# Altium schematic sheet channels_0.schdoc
size 400 x 299 mm; Device: default420x319; Symbol: default420x319; Name: default420x319; Size: "User"; Id: /; File: channels_0; Sheet: /
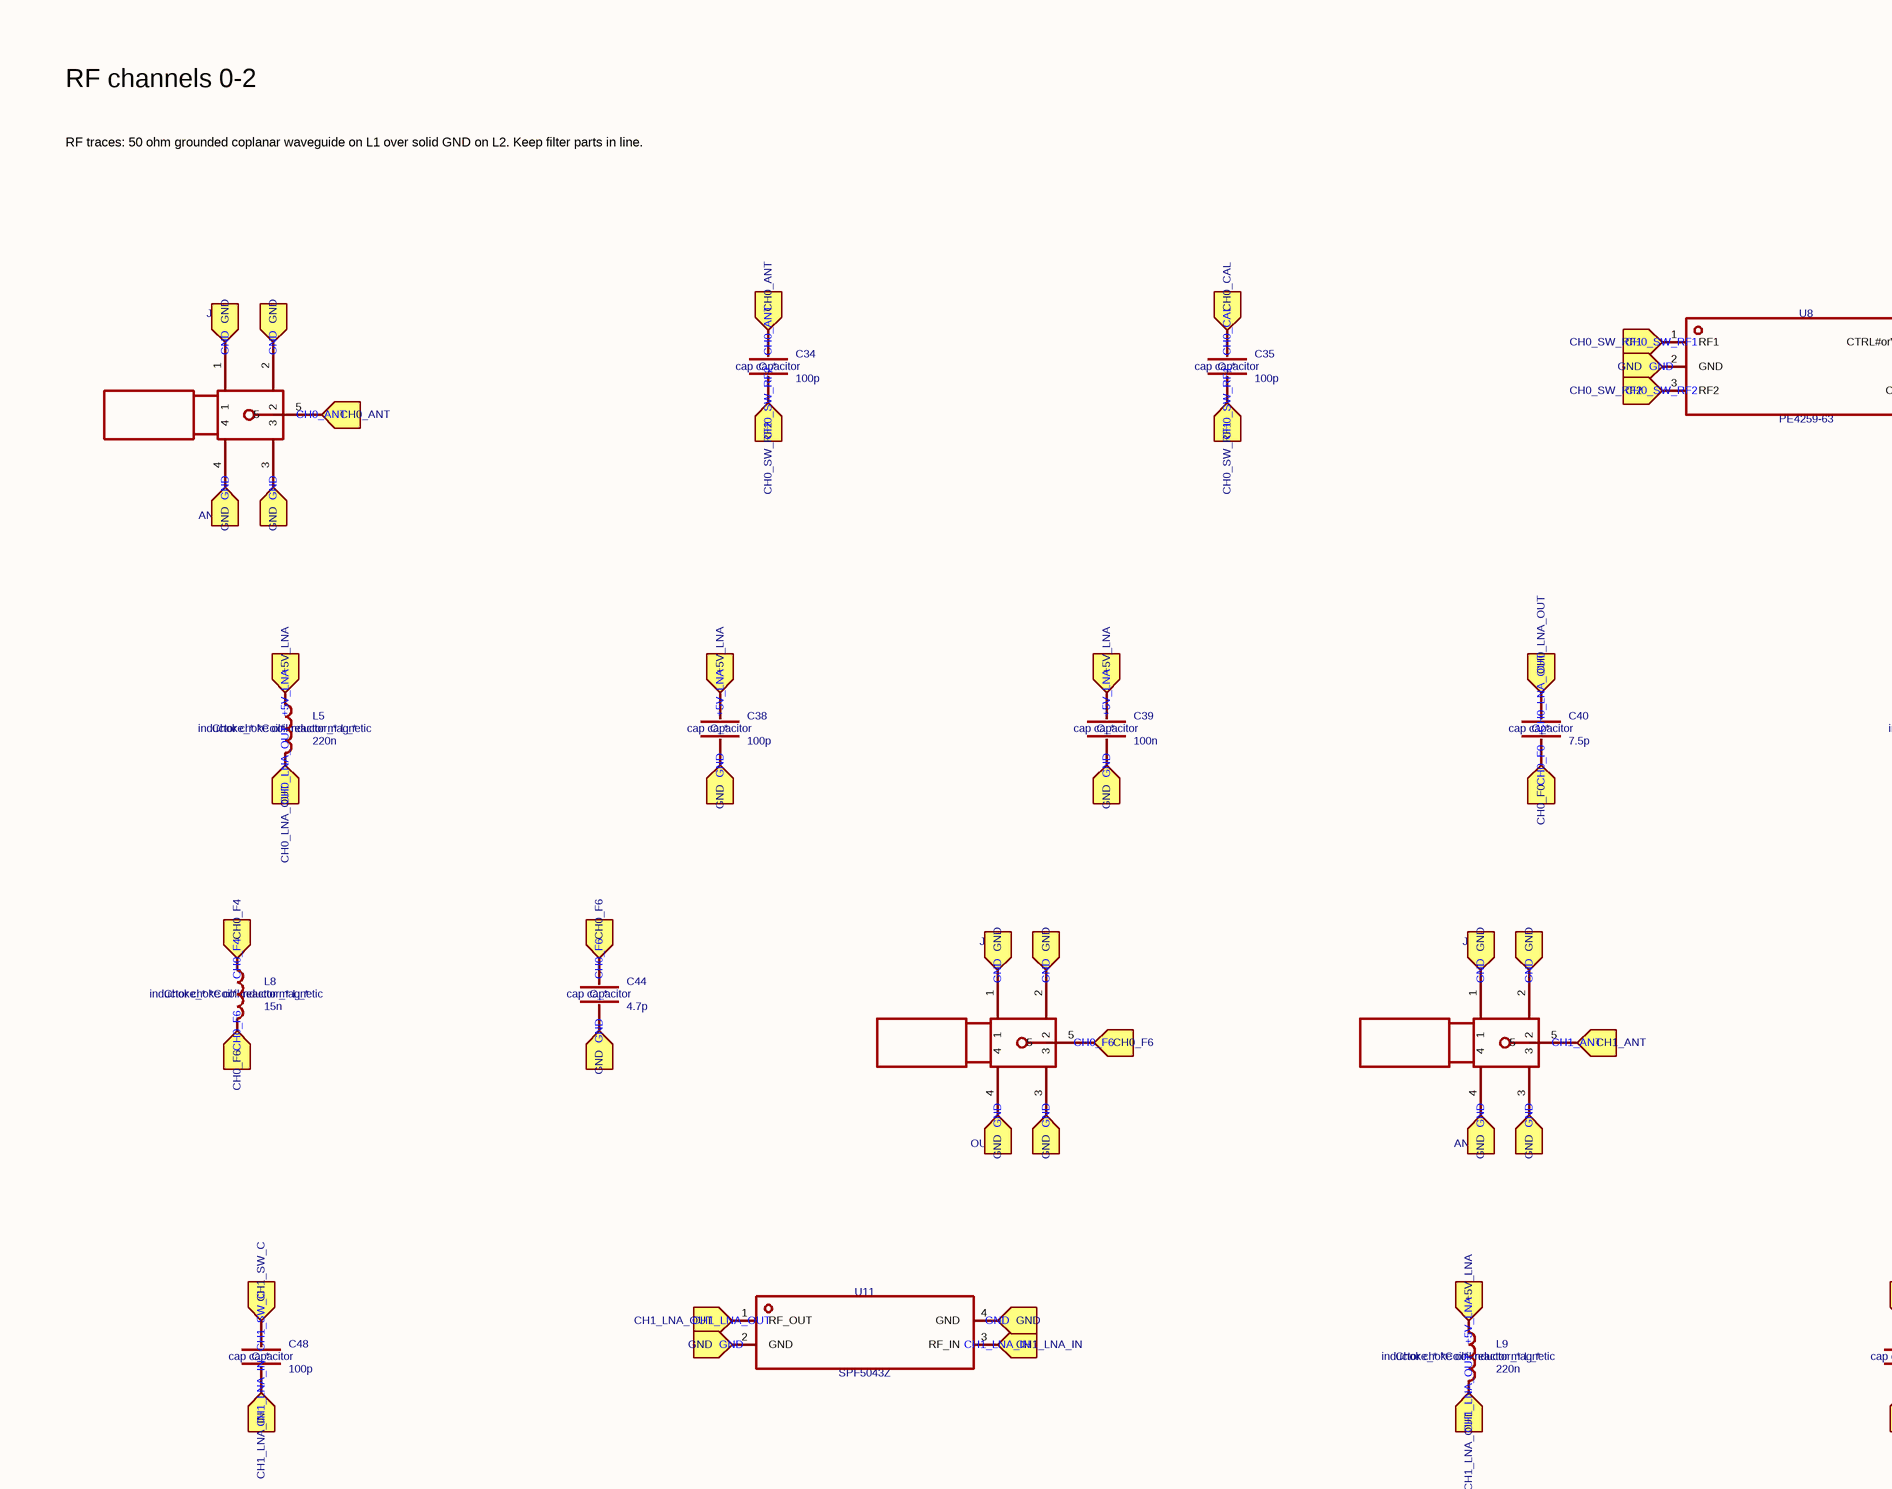
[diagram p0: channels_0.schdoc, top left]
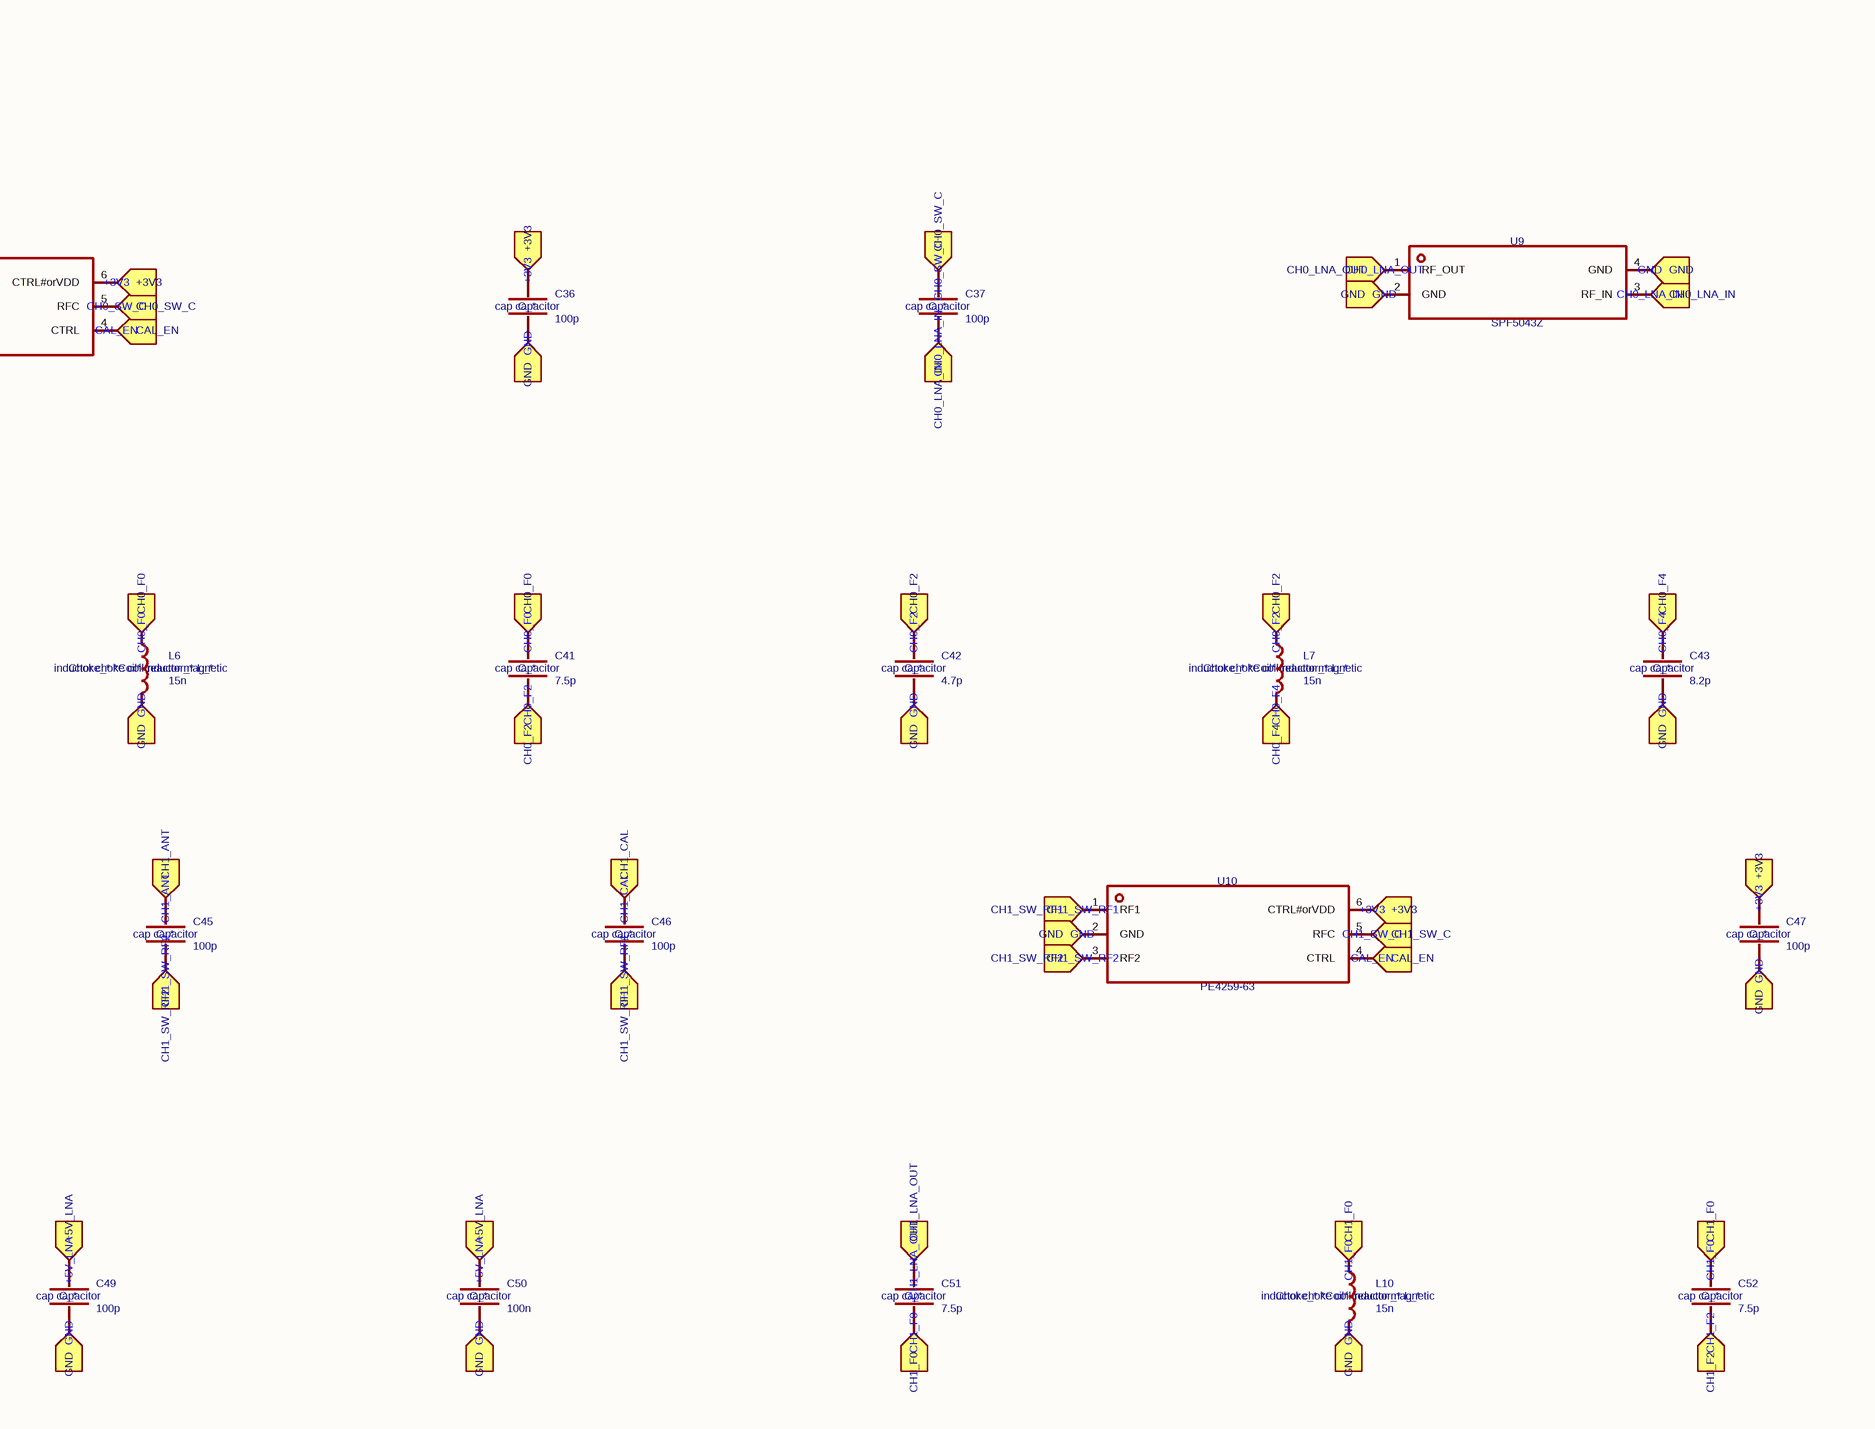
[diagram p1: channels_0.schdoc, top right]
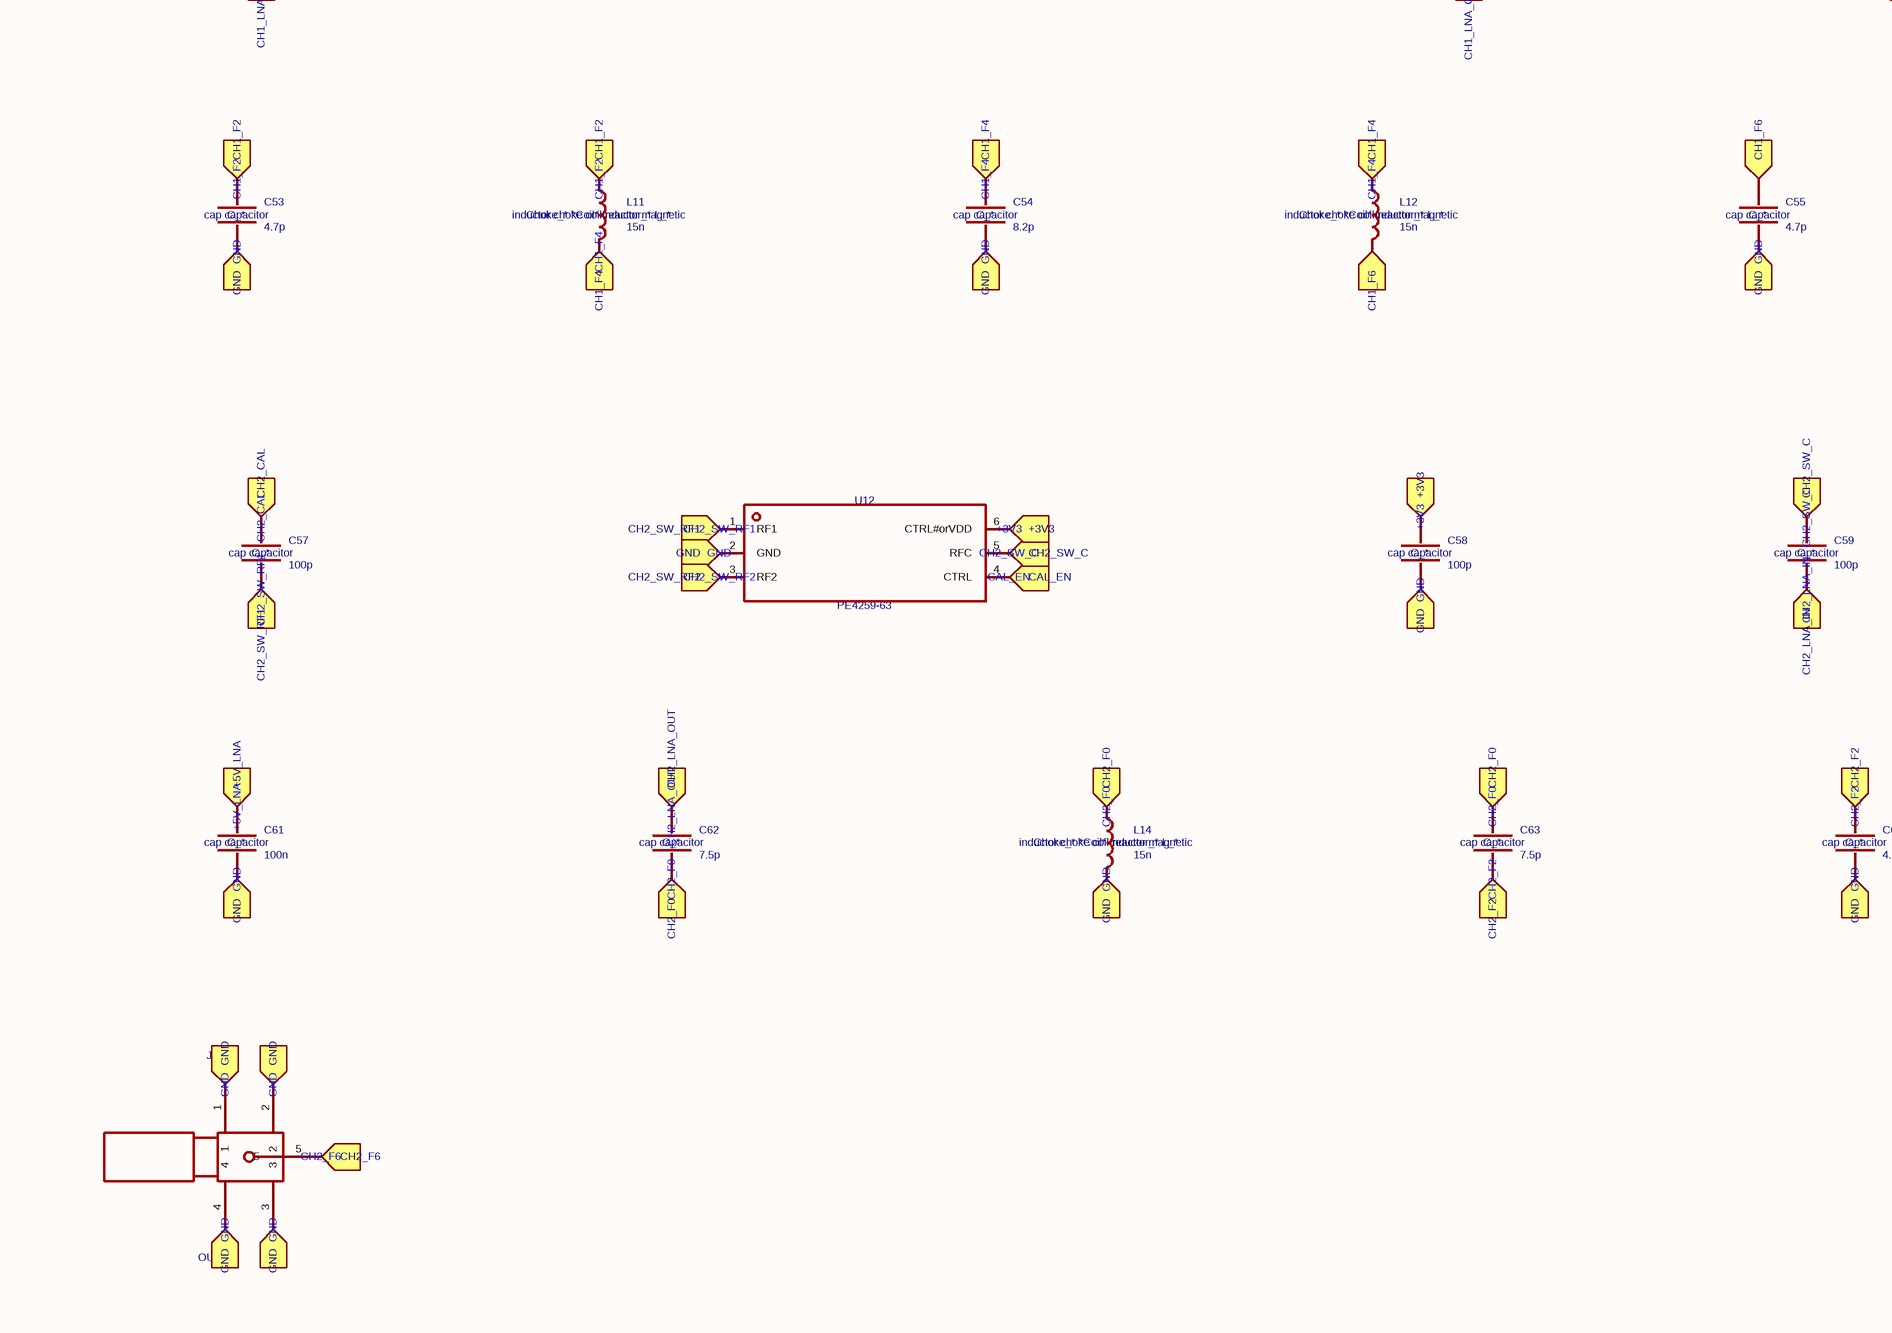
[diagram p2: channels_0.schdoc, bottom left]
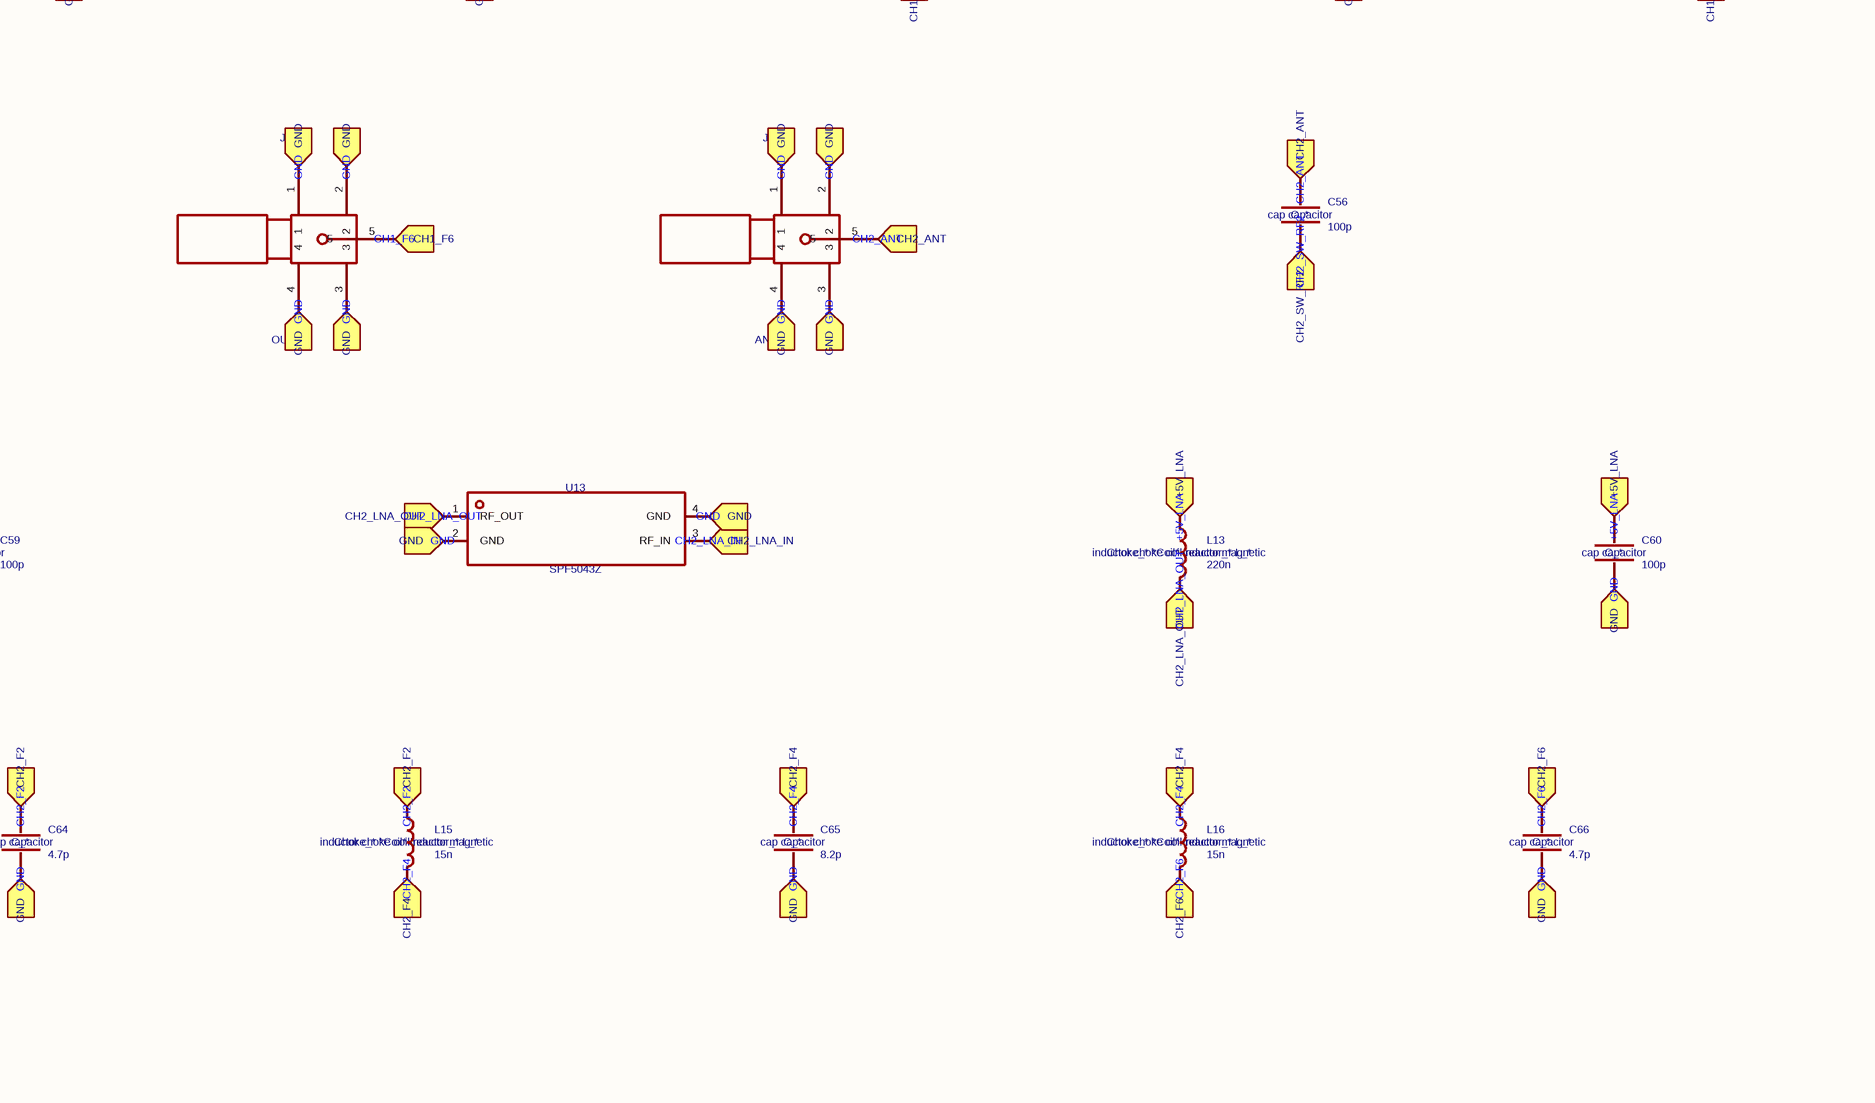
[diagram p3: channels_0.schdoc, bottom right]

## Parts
C34  value 100p  ki_keywords: cap capacitor  ki_fp_filters: C_*  [Capacitor_SMD:C_0402_1005Metric]  (hidden comment: Device_C)
C35  value 100p  ki_keywords: cap capacitor  ki_fp_filters: C_*  [Capacitor_SMD:C_0402_1005Metric]  (hidden comment: Device_C)
C36  value 100p  ki_keywords: cap capacitor  ki_fp_filters: C_*  [Capacitor_SMD:C_0402_1005Metric]  (hidden comment: Device_C)
C37  value 100p  ki_keywords: cap capacitor  ki_fp_filters: C_*  [Capacitor_SMD:C_0402_1005Metric]  (hidden comment: Device_C)
C38  value 100p  ki_keywords: cap capacitor  ki_fp_filters: C_*  [Capacitor_SMD:C_0402_1005Metric]  (hidden comment: Device_C)
C39  value 100n  ki_keywords: cap capacitor  ki_fp_filters: C_*  [Capacitor_SMD:C_0402_1005Metric]  (hidden comment: Device_C)
C40  value 7.5p  ki_keywords: cap capacitor  ki_fp_filters: C_*  [Capacitor_SMD:C_0402_1005Metric]  (hidden comment: Device_C)
C41  value 7.5p  ki_keywords: cap capacitor  ki_fp_filters: C_*  [Capacitor_SMD:C_0402_1005Metric]  (hidden comment: Device_C)
C42  value 4.7p  ki_keywords: cap capacitor  ki_fp_filters: C_*  [Capacitor_SMD:C_0402_1005Metric]  (hidden comment: Device_C)
C43  value 8.2p  ki_keywords: cap capacitor  ki_fp_filters: C_*  [Capacitor_SMD:C_0402_1005Metric]  (hidden comment: Device_C)
C44  value 4.7p  ki_keywords: cap capacitor  ki_fp_filters: C_*  [Capacitor_SMD:C_0402_1005Metric]  (hidden comment: Device_C)
C45  value 100p  ki_keywords: cap capacitor  ki_fp_filters: C_*  [Capacitor_SMD:C_0402_1005Metric]  (hidden comment: Device_C)
C46  value 100p  ki_keywords: cap capacitor  ki_fp_filters: C_*  [Capacitor_SMD:C_0402_1005Metric]  (hidden comment: Device_C)
C47  value 100p  ki_keywords: cap capacitor  ki_fp_filters: C_*  [Capacitor_SMD:C_0402_1005Metric]  (hidden comment: Device_C)
C48  value 100p  ki_keywords: cap capacitor  ki_fp_filters: C_*  [Capacitor_SMD:C_0402_1005Metric]  (hidden comment: Device_C)
C49  value 100p  ki_keywords: cap capacitor  ki_fp_filters: C_*  [Capacitor_SMD:C_0402_1005Metric]  (hidden comment: Device_C)
C50  value 100n  ki_keywords: cap capacitor  ki_fp_filters: C_*  [Capacitor_SMD:C_0402_1005Metric]  (hidden comment: Device_C)
C51  value 7.5p  ki_keywords: cap capacitor  ki_fp_filters: C_*  [Capacitor_SMD:C_0402_1005Metric]  (hidden comment: Device_C)
C52  value 7.5p  ki_keywords: cap capacitor  ki_fp_filters: C_*  [Capacitor_SMD:C_0402_1005Metric]  (hidden comment: Device_C)
C53  value 4.7p  ki_keywords: cap capacitor  ki_fp_filters: C_*  [Capacitor_SMD:C_0402_1005Metric]  (hidden comment: Device_C)
C54  value 8.2p  ki_keywords: cap capacitor  ki_fp_filters: C_*  [Capacitor_SMD:C_0402_1005Metric]  (hidden comment: Device_C)
C55  value 4.7p  ki_keywords: cap capacitor  ki_fp_filters: C_*  [Capacitor_SMD:C_0402_1005Metric]  (hidden comment: Device_C)
C56  value 100p  ki_keywords: cap capacitor  ki_fp_filters: C_*  [Capacitor_SMD:C_0402_1005Metric]  (hidden comment: Device_C)
C57  value 100p  ki_keywords: cap capacitor  ki_fp_filters: C_*  [Capacitor_SMD:C_0402_1005Metric]  (hidden comment: Device_C)
C58  value 100p  ki_keywords: cap capacitor  ki_fp_filters: C_*  [Capacitor_SMD:C_0402_1005Metric]  (hidden comment: Device_C)
C59  value 100p  ki_keywords: cap capacitor  ki_fp_filters: C_*  [Capacitor_SMD:C_0402_1005Metric]  (hidden comment: Device_C)
C60  value 100p  ki_keywords: cap capacitor  ki_fp_filters: C_*  [Capacitor_SMD:C_0402_1005Metric]  (hidden comment: Device_C)
C61  value 100n  ki_keywords: cap capacitor  ki_fp_filters: C_*  [Capacitor_SMD:C_0402_1005Metric]  (hidden comment: Device_C)
C62  value 7.5p  ki_keywords: cap capacitor  ki_fp_filters: C_*  [Capacitor_SMD:C_0402_1005Metric]  (hidden comment: Device_C)
C63  value 7.5p  ki_keywords: cap capacitor  ki_fp_filters: C_*  [Capacitor_SMD:C_0402_1005Metric]  (hidden comment: Device_C)
C64  value 4.7p  ki_keywords: cap capacitor  ki_fp_filters: C_*  [Capacitor_SMD:C_0402_1005Metric]  (hidden comment: Device_C)
C65  value 8.2p  ki_keywords: cap capacitor  ki_fp_filters: C_*  [Capacitor_SMD:C_0402_1005Metric]  (hidden comment: Device_C)
C66  value 4.7p  ki_keywords: cap capacitor  ki_fp_filters: C_*  [Capacitor_SMD:C_0402_1005Metric]  (hidden comment: Device_C)
J3  value ANT0  [prc:SMA-TH_BWSMA-KE-Z001]  (hidden comment: prc_BWSMA-KE-Z001)
J4  value OUT0  [prc:SMA-TH_BWSMA-KE-Z001]  (hidden comment: prc_BWSMA-KE-Z001)
J5  value ANT1  [prc:SMA-TH_BWSMA-KE-Z001]  (hidden comment: prc_BWSMA-KE-Z001)
J6  value OUT1  [prc:SMA-TH_BWSMA-KE-Z001]  (hidden comment: prc_BWSMA-KE-Z001)
J7  value ANT2  [prc:SMA-TH_BWSMA-KE-Z001]  (hidden comment: prc_BWSMA-KE-Z001)
J8  value OUT2  [prc:SMA-TH_BWSMA-KE-Z001]  (hidden comment: prc_BWSMA-KE-Z001)
L5  value 220n  ki_keywords: inductor choke coil reactor magnetic  ki_fp_filters: Choke_* *Coil* Inductor_* L_*  [Inductor_SMD:L_0603_1608Metric]  (hidden comment: Device_L)
L6  value 15n  ki_keywords: inductor choke coil reactor magnetic  ki_fp_filters: Choke_* *Coil* Inductor_* L_*  [Inductor_SMD:L_0402_1005Metric]  (hidden comment: Device_L)
L7  value 15n  ki_keywords: inductor choke coil reactor magnetic  ki_fp_filters: Choke_* *Coil* Inductor_* L_*  [Inductor_SMD:L_0402_1005Metric]  (hidden comment: Device_L)
L8  value 15n  ki_keywords: inductor choke coil reactor magnetic  ki_fp_filters: Choke_* *Coil* Inductor_* L_*  [Inductor_SMD:L_0402_1005Metric]  (hidden comment: Device_L)
L9  value 220n  ki_keywords: inductor choke coil reactor magnetic  ki_fp_filters: Choke_* *Coil* Inductor_* L_*  [Inductor_SMD:L_0603_1608Metric]  (hidden comment: Device_L)
L10  value 15n  ki_keywords: inductor choke coil reactor magnetic  ki_fp_filters: Choke_* *Coil* Inductor_* L_*  [Inductor_SMD:L_0402_1005Metric]  (hidden comment: Device_L)
L11  value 15n  ki_keywords: inductor choke coil reactor magnetic  ki_fp_filters: Choke_* *Coil* Inductor_* L_*  [Inductor_SMD:L_0402_1005Metric]  (hidden comment: Device_L)
L12  value 15n  ki_keywords: inductor choke coil reactor magnetic  ki_fp_filters: Choke_* *Coil* Inductor_* L_*  [Inductor_SMD:L_0402_1005Metric]  (hidden comment: Device_L)
L13  value 220n  ki_keywords: inductor choke coil reactor magnetic  ki_fp_filters: Choke_* *Coil* Inductor_* L_*  [Inductor_SMD:L_0603_1608Metric]  (hidden comment: Device_L)
L14  value 15n  ki_keywords: inductor choke coil reactor magnetic  ki_fp_filters: Choke_* *Coil* Inductor_* L_*  [Inductor_SMD:L_0402_1005Metric]  (hidden comment: Device_L)
L15  value 15n  ki_keywords: inductor choke coil reactor magnetic  ki_fp_filters: Choke_* *Coil* Inductor_* L_*  [Inductor_SMD:L_0402_1005Metric]  (hidden comment: Device_L)
L16  value 15n  ki_keywords: inductor choke coil reactor magnetic  ki_fp_filters: Choke_* *Coil* Inductor_* L_*  [Inductor_SMD:L_0402_1005Metric]  (hidden comment: Device_L)
U8  value PE4259-63  [prc:SC-70-6_L2.2-W1.3-P0.65-LS2.1-BL]  (hidden comment: prc_PE4259-63)
U9  value SPF5043Z  [prc:SOT343_L2.0-W1.3-P1.30-LS2.1-BL]  (hidden comment: prc_SPF5043Z)
U10  value PE4259-63  [prc:SC-70-6_L2.2-W1.3-P0.65-LS2.1-BL]  (hidden comment: prc_PE4259-63)
U11  value SPF5043Z  [prc:SOT343_L2.0-W1.3-P1.30-LS2.1-BL]  (hidden comment: prc_SPF5043Z)
U12  value PE4259-63  [prc:SC-70-6_L2.2-W1.3-P0.65-LS2.1-BL]  (hidden comment: prc_PE4259-63)
U13  value SPF5043Z  [prc:SOT343_L2.0-W1.3-P1.30-LS2.1-BL]  (hidden comment: prc_SPF5043Z)

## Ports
+3V3 (in), +5V_LNA (in), CAL_EN (in), CH0_ANT (in), CH0_CAL (in), CH0_F0 (in), CH0_F2 (in), CH0_F4 (in), CH0_F6 (in), CH0_LNA_IN (in), CH0_LNA_OUT (in), CH0_SW_C (in), CH0_SW_RF1 (in), CH0_SW_RF2 (in), CH1_ANT (in), CH1_CAL (in), CH1_F0 (in), CH1_F2 (in), CH1_F4 (in), CH1_F6 (in), CH1_LNA_IN (in), CH1_LNA_OUT (in), CH1_SW_C (in), CH1_SW_RF1 (in), CH1_SW_RF2 (in), CH2_ANT (in), CH2_CAL (in), CH2_F0 (in), CH2_F2 (in), CH2_F4 (in), CH2_F6 (in), CH2_LNA_IN (in), CH2_LNA_OUT (in), CH2_SW_C (in), CH2_SW_RF1 (in), CH2_SW_RF2 (in), GND (in)

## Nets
+3V3: C36.1 C47.1 C58.1 U8.6(CTRL#orVDD) U10.6(CTRL#orVDD) U12.6(CTRL#orVDD) ; port +3V3
+5V_LNA: C38.1 C39.1 C49.1 C50.1 C60.1 C61.1 L5.1 L9.1 L13.1 ; port +5V_LNA
CAL_EN: U8.4(CTRL) U10.4(CTRL) U12.4(CTRL) ; port CAL_EN
CH0_ANT: C34.1 J3.5 ; port CH0_ANT
CH0_CAL: C35.1 ; port CH0_CAL
CH0_F0: C40.2 C41.1 L6.1 ; port CH0_F0
CH0_F2: C41.2 C42.1 L7.1 ; port CH0_F2
CH0_F4: C43.1 L7.2 L8.1 ; port CH0_F4
CH0_F6: C44.1 J4.5 L8.2 ; port CH0_F6
CH0_LNA_IN: C37.2 U9.3(RF_IN) ; port CH0_LNA_IN
CH0_LNA_OUT: C40.1 L5.2 U9.1(RF_OUT) ; port CH0_LNA_OUT
CH0_SW_C: C37.1 U8.5(RFC) ; port CH0_SW_C
CH0_SW_RF1: C35.2 U8.1(RF1) ; port CH0_SW_RF1
CH0_SW_RF2: C34.2 U8.3(RF2) ; port CH0_SW_RF2
CH1_ANT: C45.1 J5.5 ; port CH1_ANT
CH1_CAL: C46.1 ; port CH1_CAL
CH1_F0: C51.2 C52.1 L10.1 ; port CH1_F0
CH1_F2: C52.2 C53.1 L11.1 ; port CH1_F2
CH1_F4: C54.1 L11.2 L12.1 ; port CH1_F4
CH1_F6: C55.1 J6.5 L12.2 ; port CH1_F6
CH1_LNA_IN: C48.2 U11.3(RF_IN) ; port CH1_LNA_IN
CH1_LNA_OUT: C51.1 L9.2 U11.1(RF_OUT) ; port CH1_LNA_OUT
CH1_SW_C: C48.1 U10.5(RFC) ; port CH1_SW_C
CH1_SW_RF1: C46.2 U10.1(RF1) ; port CH1_SW_RF1
CH1_SW_RF2: C45.2 U10.3(RF2) ; port CH1_SW_RF2
CH2_ANT: C56.1 J7.5 ; port CH2_ANT
CH2_CAL: C57.1 ; port CH2_CAL
CH2_F0: C62.2 C63.1 L14.1 ; port CH2_F0
CH2_F2: C63.2 C64.1 L15.1 ; port CH2_F2
CH2_F4: C65.1 L15.2 L16.1 ; port CH2_F4
CH2_F6: C66.1 J8.5 L16.2 ; port CH2_F6
CH2_LNA_IN: C59.2 U13.3(RF_IN) ; port CH2_LNA_IN
CH2_LNA_OUT: C62.1 L13.2 U13.1(RF_OUT) ; port CH2_LNA_OUT
CH2_SW_C: C59.1 U12.5(RFC) ; port CH2_SW_C
CH2_SW_RF1: C57.2 U12.1(RF1) ; port CH2_SW_RF1
CH2_SW_RF2: C56.2 U12.3(RF2) ; port CH2_SW_RF2
GND: C36.2 C38.2 C39.2 C42.2 C43.2 C44.2 C47.2 C49.2 C50.2 C53.2 C54.2 C55.2 C58.2 C60.2 C61.2 C64.2 C65.2 C66.2 J3.1 J3.2 J3.3 J3.4 J4.1 J4.2 J4.3 J4.4 J5.1 J5.2 J5.3 J5.4 J6.1 J6.2 J6.3 J6.4 J7.1 J7.2 J7.3 J7.4 J8.1 J8.2 J8.3 J8.4 L6.2 L10.2 L14.2 U8.2(GND) U9.2(GND) U9.4(GND) U10.2(GND) U11.2(GND) U11.4(GND) U12.2(GND) U13.2(GND) U13.4(GND) ; port GND

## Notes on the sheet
- RF channels 0-2
- RF traces: 50 ohm grounded coplanar waveguide on L1 over solid GND on L2. Keep filter parts in line.

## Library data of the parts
C34 = Device_C: UniqueId: 553def7d7947fca6; KiLib_Generator: SMD_2terminal_chip_molded; AddInBom: yes
C35 = Device_C: UniqueId: 2b4e6e580c7acde0; KiLib_Generator: SMD_2terminal_chip_molded; AddInBom: yes
C36 = Device_C: UniqueId: 3db1f6a400993974; KiLib_Generator: SMD_2terminal_chip_molded; AddInBom: yes
C37 = Device_C: UniqueId: ff078052695da6b6; KiLib_Generator: SMD_2terminal_chip_molded; AddInBom: yes
C38 = Device_C: UniqueId: 6827ca7a6bd67e26; KiLib_Generator: SMD_2terminal_chip_molded; AddInBom: yes
C39 = Device_C: UniqueId: 54d3d224326b3f8f; KiLib_Generator: SMD_2terminal_chip_molded; AddInBom: yes
C40 = Device_C: UniqueId: 12af2948e5a85261; KiLib_Generator: SMD_2terminal_chip_molded; AddInBom: yes
C41 = Device_C: UniqueId: c9655d0faea7d93e; KiLib_Generator: SMD_2terminal_chip_molded; AddInBom: yes
C42 = Device_C: UniqueId: d39ee3bf0fadc3c1; KiLib_Generator: SMD_2terminal_chip_molded; AddInBom: yes
C43 = Device_C: UniqueId: ad7e9e1612356ddb; KiLib_Generator: SMD_2terminal_chip_molded; AddInBom: yes
C44 = Device_C: UniqueId: 49133e3f49d3504d; KiLib_Generator: SMD_2terminal_chip_molded; AddInBom: yes
C45 = Device_C: UniqueId: 9dabde1b2911a551; KiLib_Generator: SMD_2terminal_chip_molded; AddInBom: yes
C46 = Device_C: UniqueId: df918f74c5ced612; KiLib_Generator: SMD_2terminal_chip_molded; AddInBom: yes
C47 = Device_C: UniqueId: 64621f1995cfd5bc; KiLib_Generator: SMD_2terminal_chip_molded; AddInBom: yes
C48 = Device_C: UniqueId: 808ebf677d8d6d64; KiLib_Generator: SMD_2terminal_chip_molded; AddInBom: yes
C49 = Device_C: UniqueId: 91fd74edebd22ea1; KiLib_Generator: SMD_2terminal_chip_molded; AddInBom: yes
C50 = Device_C: UniqueId: 32f6df7045cd6eaa; KiLib_Generator: SMD_2terminal_chip_molded; AddInBom: yes
C51 = Device_C: UniqueId: d35436b77a732af0; KiLib_Generator: SMD_2terminal_chip_molded; AddInBom: yes
C52 = Device_C: UniqueId: 35d858017be1d91e; KiLib_Generator: SMD_2terminal_chip_molded; AddInBom: yes
C53 = Device_C: UniqueId: af7046427a4bfdfb; KiLib_Generator: SMD_2terminal_chip_molded; AddInBom: yes
C54 = Device_C: UniqueId: 65328433fb04ddb7; KiLib_Generator: SMD_2terminal_chip_molded; AddInBom: yes
C55 = Device_C: UniqueId: 82ba1af55b3917e5; KiLib_Generator: SMD_2terminal_chip_molded; AddInBom: yes
C56 = Device_C: UniqueId: a22d741cda083e99; KiLib_Generator: SMD_2terminal_chip_molded; AddInBom: yes
C57 = Device_C: UniqueId: 21dd5459dde3f81c; KiLib_Generator: SMD_2terminal_chip_molded; AddInBom: yes
C58 = Device_C: UniqueId: 6c1fb86984bf7302; KiLib_Generator: SMD_2terminal_chip_molded; AddInBom: yes
C59 = Device_C: UniqueId: 9b91e7356bb9865f; KiLib_Generator: SMD_2terminal_chip_molded; AddInBom: yes
C60 = Device_C: UniqueId: 769677d4f8f56233; KiLib_Generator: SMD_2terminal_chip_molded; AddInBom: yes
C61 = Device_C: UniqueId: 3745dda5a27601a3; KiLib_Generator: SMD_2terminal_chip_molded; AddInBom: yes
C62 = Device_C: UniqueId: 4b556904310d1556; KiLib_Generator: SMD_2terminal_chip_molded; AddInBom: yes
C63 = Device_C: UniqueId: b3cb865a57c4a975; KiLib_Generator: SMD_2terminal_chip_molded; AddInBom: yes
C64 = Device_C: UniqueId: 9944326385f1aa7b; KiLib_Generator: SMD_2terminal_chip_molded; AddInBom: yes
C65 = Device_C: UniqueId: ac9f836745bfd3f0; KiLib_Generator: SMD_2terminal_chip_molded; AddInBom: yes
C66 = Device_C: UniqueId: fb27f7370dbf7a2e; KiLib_Generator: SMD_2terminal_chip_molded; AddInBom: yes
J3 = prc_BWSMA-KE-Z001: Manufacturer: BAT WIRELESS(蝙蝠无线); ki_keywords: RF Connectors / Coaxial Connectors; UniqueId: bd3ee0abdb58119f; AddInBom: yes
J4 = prc_BWSMA-KE-Z001: Manufacturer: BAT WIRELESS(蝙蝠无线); ki_keywords: RF Connectors / Coaxial Connectors; UniqueId: 7aadee231938cadd; AddInBom: yes
J5 = prc_BWSMA-KE-Z001: Manufacturer: BAT WIRELESS(蝙蝠无线); ki_keywords: RF Connectors / Coaxial Connectors; UniqueId: 188f82074eb8ca32; AddInBom: yes
J6 = prc_BWSMA-KE-Z001: Manufacturer: BAT WIRELESS(蝙蝠无线); ki_keywords: RF Connectors / Coaxial Connectors; UniqueId: be1703a8306ee88a; AddInBom: yes
J7 = prc_BWSMA-KE-Z001: Manufacturer: BAT WIRELESS(蝙蝠无线); ki_keywords: RF Connectors / Coaxial Connectors; UniqueId: adeb8d5268617f3b; AddInBom: yes
J8 = prc_BWSMA-KE-Z001: Manufacturer: BAT WIRELESS(蝙蝠无线); ki_keywords: RF Connectors / Coaxial Connectors; UniqueId: 5c2e899d33916bcd; AddInBom: yes
L5 = Device_L: UniqueId: a672ad5603fb0b7d; KiLib_Generator: SMD_2terminal_chip_molded; AddInBom: yes
L6 = Device_L: UniqueId: 47af25b8573c8ed0; KiLib_Generator: SMD_2terminal_chip_molded; AddInBom: yes
L7 = Device_L: UniqueId: 6645345e349bedbf; KiLib_Generator: SMD_2terminal_chip_molded; AddInBom: yes
L8 = Device_L: UniqueId: 75e42c17a1aecd44; KiLib_Generator: SMD_2terminal_chip_molded; AddInBom: yes
L9 = Device_L: UniqueId: d117b5b224b2d503; KiLib_Generator: SMD_2terminal_chip_molded; AddInBom: yes
L10 = Device_L: UniqueId: 0449f3f0b77b5331; KiLib_Generator: SMD_2terminal_chip_molded; AddInBom: yes
L11 = Device_L: UniqueId: 0b48be2b02231b9b; KiLib_Generator: SMD_2terminal_chip_molded; AddInBom: yes
L12 = Device_L: UniqueId: 17da6896838d082f; KiLib_Generator: SMD_2terminal_chip_molded; AddInBom: yes
L13 = Device_L: UniqueId: 4c6c9a142d4a9dea; KiLib_Generator: SMD_2terminal_chip_molded; AddInBom: yes
L14 = Device_L: UniqueId: 98f88dbce3f84684; KiLib_Generator: SMD_2terminal_chip_molded; AddInBom: yes
L15 = Device_L: UniqueId: 6e1bc876f58b9a76; KiLib_Generator: SMD_2terminal_chip_molded; AddInBom: yes
L16 = Device_L: UniqueId: c155a61d248d9d24; KiLib_Generator: SMD_2terminal_chip_molded; AddInBom: yes
U8 = prc_PE4259-63: Manufacturer: pSemi(游隼半导体); ki_keywords: RF Switches; UniqueId: 484e3008dca2bfa8; AddInBom: yes
U9 = prc_SPF5043Z: Manufacturer: Qorvo; ki_keywords: RF Amplifiers; UniqueId: 2dbbb3175ebf36d7; AddInBom: yes
U10 = prc_PE4259-63: Manufacturer: pSemi(游隼半导体); ki_keywords: RF Switches; UniqueId: c69de7c088414df5; AddInBom: yes
U11 = prc_SPF5043Z: Manufacturer: Qorvo; ki_keywords: RF Amplifiers; UniqueId: 2fd166bdb6936536; AddInBom: yes
U12 = prc_PE4259-63: Manufacturer: pSemi(游隼半导体); ki_keywords: RF Switches; UniqueId: b6112465b0588c80; AddInBom: yes
U13 = prc_SPF5043Z: Manufacturer: Qorvo; ki_keywords: RF Amplifiers; UniqueId: 95e557ff5ab9d76b; AddInBom: yes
